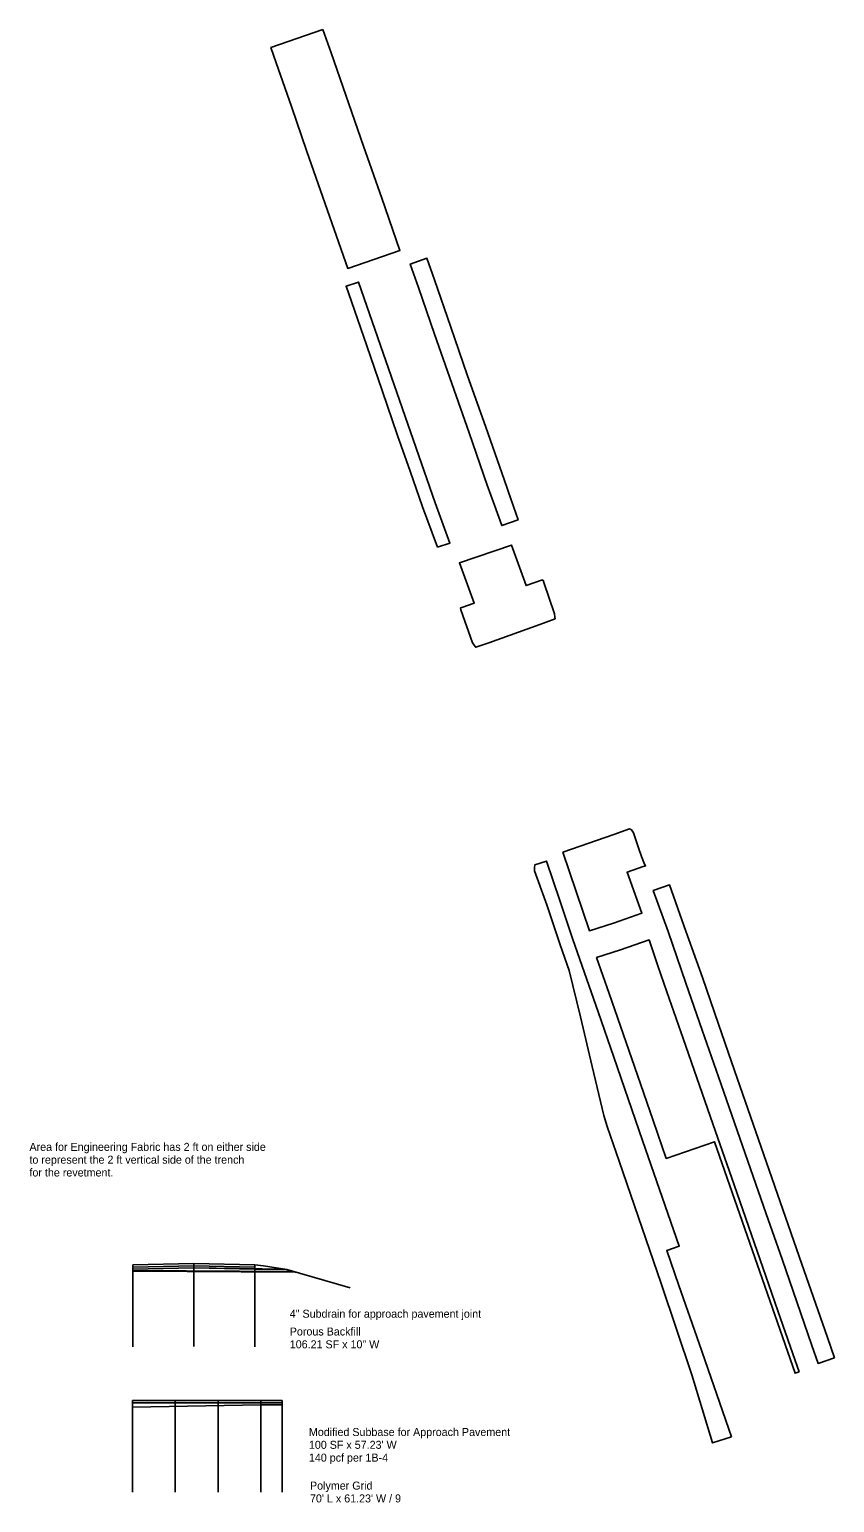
# Model space of a CAD drawing. Extents: x 16416320 to 16418266, y 7115195 to 7120678.
# Drawn here: x 16417426 to 16417803, y 7117848 to 7118538 of the extents above; entities that cross this region are included whole.
import ezdxf

# ---------------------------------------------------------------- set-up
doc = ezdxf.new("R2010")
doc.units = 0
for name, color, linetype in [('Default', 7, 'Continuous'), ('PS_BOLT', 7, 'Continuous'), ('PS_SHAPE', 7, 'Continuous'), ('PS_WORKFRAME', 7, 'Continuous'), ('Terrain', 7, 'Continuous')]:
    doc.layers.add(name, color=color, linetype=linetype)

msp = doc.modelspace()

# ---------------------------------------------------------------- linework, layer by layer
at = {"layer": 'Default'}
for p, q in [((16417474.07, 7117959), (16417502.68, 7117959.57)), ((16417474.07, 7117959), (16417474.07, 7117920.58)), ((16417474.07, 7117958), (16417502.68, 7117958.57)), ((16417474.07, 7117957), (16417502.68, 7117957.57)), ((16417502.68, 7117959.57), (16417502.68, 7117920.74)), ((16417531.3, 7117959), (16417502.68, 7117959.57)), ((16417531.3, 7117958), (16417502.68, 7117958.57)), ((16417531.3, 7117957), (16417502.68, 7117957.57)), ((16417531.3, 7117959), (16417531.3, 7117920.58)), ((16417531.3, 7117959), (16417535.3, 7117958.6)), ((16417531.3, 7117957), (16417545.32, 7117956.93)), ((16417535.3, 7117958.6), (16417546.19, 7117956.78)), ((16417474.09, 7117956.33), (16417549.08, 7117955.95)), ((16417474.09, 7117956), (16417550.27, 7117955.62)), ((16417546.19, 7117956.78), (16417575.9, 7117948.29)), ((16417474.02, 7117895.4), (16417474.02, 7117852.47)), ((16417474.02, 7117895.4), (16417544.02, 7117895.4)), ((16417494.02, 7117895.4), (16417494.02, 7117852.47)), ((16417514.02, 7117895.4), (16417514.02, 7117852.47)), ((16417534.02, 7117895.4), (16417534.02, 7117852.47)), ((16417544.02, 7117895.4), (16417544.02, 7117852.47)), ((16417474.02, 7117894.4), (16417544.02, 7117894.4)), ((16417474.02, 7117892.4), (16417534.02, 7117893.4)), ((16417534.02, 7117893.4), (16417544.02, 7117893.4))]:
    msp.add_line(p, q, dxfattribs=at)
msp.add_lwpolyline([(16417474.09, 7117956), (16417550.27, 7117955.62), (16417549.08, 7117955.95), (16417474.09, 7117956.33)], close=True, dxfattribs=at)
at = {"layer": 'PS_BOLT'}
for points in [[(16417563.16, 7118537.73), (16417566.98, 7118526.75), (16417582.13, 7118483.1), (16417590.67, 7118458.64), (16417599.21, 7118434.19), (16417574.74, 7118425.82), (16417555.65, 7118480.53), (16417548.47, 7118501.57), (16417541.32, 7118522.15), (16417538.83, 7118529.28)], [(16417654.54, 7118307.97), (16417646.89, 7118305.32), (16417643.5, 7118314.81), (16417640.11, 7118324.3), (16417631.57, 7118348.76), (16417615.45, 7118395.04), (16417607.88, 7118416.87), (16417604.06, 7118427.85), (16417611.87, 7118430.56), (16417615.37, 7118420.4), (16417623.03, 7118398.2), (16417630.68, 7118376), (16417639.38, 7118351.44), (16417648.07, 7118326.88), (16417651.31, 7118317.42)], [(16417616.8, 7118295.14), (16417616.8, 7118295.14), (16417609.73, 7118314.09), (16417603.93, 7118330.79), (16417598.13, 7118347.49), (16417590.89, 7118368.54), (16417583.66, 7118389.59), (16417576.47, 7118410.35), (16417574.02, 7118417.42), (16417579.73, 7118419.4), (16417615.64, 7118315.94), (16417622.59, 7118297.05)], [(16417671.81, 7118261.67), (16417664.77, 7118258.94), (16417640.75, 7118250.45), (16417634.77, 7118248.36), (16417634.5, 7118248.58), (16417634.45, 7118248.72), (16417633.17, 7118250.45), (16417627.73, 7118265.88), (16417627.56, 7118266.85), (16417628.18, 7118267.01), (16417633.91, 7118268.9), (16417633.96, 7118268.93), (16417627.02, 7118287.81), (16417651.49, 7118296.17), (16417658.27, 7118277.19), (16417665.92, 7118279.84), (16417665.91, 7118279.62), (16417666.24, 7118279.71), (16417666.63, 7118278.66), (16417669.09, 7118271.35), (16417671.54, 7118264.05), (16417671.75, 7118262.37)], [(16417675.54, 7118152.26), (16417699.28, 7118160.61), (16417706.76, 7118163.3), (16417707.6, 7118162.74), (16417708.61, 7118161.38), (16417710.99, 7118153.95), (16417712.32, 7118150.36), (16417713.66, 7118146.77), (16417714.21, 7118145.92), (16417713.68, 7118145.7), (16417713.15, 7118145.57), (16417705.52, 7118142.91), (16417712.52, 7118123.77), (16417699.16, 7118119.05), (16417687.93, 7118115.51)], [(16417754.43, 7117878.48), (16417745.58, 7117875.63), (16417735.91, 7117907.55), (16417721.53, 7117950.3), (16417721.53, 7117950.3), (16417701.81, 7118007.59), (16417696.23, 7118023.8), (16417694.71, 7118029.02), (16417689.2, 7118051.88), (16417683.68, 7118075.2), (16417678.47, 7118096.92), (16417674.27, 7118108.93), (16417668, 7118127.61), (16417662.27, 7118143.59), (16417662.16, 7118145.46), (16417662.39, 7118146.08), (16417662.42, 7118146.42), (16417667.8, 7118148.12), (16417673.99, 7118129.74), (16417680.19, 7118111.37), (16417691.97, 7118077.51), (16417699.36, 7118056.23), (16417712.8, 7118017.21), (16417729.97, 7117967.76), (16417724.13, 7117965.73), (16417729.84, 7117949.3), (16417739.28, 7117922.11)], [(16417802.68, 7117915.48), (16417795.01, 7117912.82), (16417792.05, 7117921.29), (16417778.13, 7117961.69), (16417770.75, 7117982.83), (16417763.37, 7118003.98), (16417748.42, 7118047.02), (16417740.76, 7118068.96), (16417733.11, 7118090.9), (16417724.81, 7118115.21), (16417717.81, 7118134.36), (16417725.43, 7118137.01), (16417733.13, 7118115.32), (16417740.82, 7118093.62), (16417748.37, 7118071.8), (16417755.92, 7118049.99), (16417763.38, 7118028.5), (16417770.84, 7118007.01), (16417778.48, 7117984.97), (16417786.12, 7117962.93), (16417799.38, 7117924.91)], [(16417786.05, 7117908.85), (16417784.22, 7117908.21), (16417746.54, 7118016.71), (16417723.87, 7118008.83), (16417717.83, 7118026.57), (16417710.43, 7118047.85), (16417697.15, 7118086.06), (16417691.26, 7118102.98), (16417702.49, 7118106.52), (16417709.17, 7118108.88), (16417715.85, 7118111.24), (16417720, 7118099.09), (16417724.15, 7118086.93), (16417731.81, 7118064.99), (16417739.46, 7118043.05), (16417746.94, 7118021.53), (16417754.41, 7118000.01), (16417769.17, 7117957.72), (16417776.13, 7117937.52), (16417783.09, 7117917.32)]]:
    msp.add_lwpolyline(points, close=True, dxfattribs=at)
at = {"layer": 'PS_SHAPE'}
msp.add_lwpolyline([(16417474.09, 7117956), (16417474.07, 7117957), (16417502.68, 7117957.57), (16417545.32, 7117956.93), (16417546.19, 7117956.78), (16417550.27, 7117955.62)], close=True, dxfattribs=at)
at = {"layer": 'PS_WORKFRAME'}
msp.add_lwpolyline([(16417474.02, 7117892.4), (16417474.02, 7117894.4), (16417544.02, 7117894.4), (16417544.02, 7117893.4), (16417534.02, 7117893.4)], close=True, dxfattribs=at)

# ---------------------------------------------------------------- texts
at = {"layer": 'Default'}
for s, p in [('4" Subdrain for approach pavement joint', (16417547.62, 7117934.24)), ('Polymer Grid', (16417557.09, 7117853.72)), ("70' L x 61.23' W / 9", (16417557.09, 7117847.72))]:
    msp.add_text(s, height=3.75, dxfattribs=at).set_placement(p)
at = {"layer": 'PS_SHAPE'}
for s, p in [('Porous Backfill', (16417547.62, 7117925.91)), ('106.21 SF x 10" W', (16417547.62, 7117919.91))]:
    msp.add_text(s, height=3.75, dxfattribs=at).set_placement(p)
at = {"layer": 'PS_WORKFRAME'}
for s, p in [('Modified Subbase for Approach Pavement', (16417556.58, 7117878.83)), ("100 SF x 57.23' W", (16417556.58, 7117872.83)), ('140 pcf per 1B-4', (16417556.58, 7117866.83))]:
    msp.add_text(s, height=3.75, dxfattribs=at).set_placement(p)
at = {"layer": 'Terrain'}
for s, p in [('Area for Engineering Fabric has 2 ft on either side', (16417425.74, 7118012.4)), ('to represent the 2 ft vertical side of the trench', (16417425.74, 7118006.4)), ('for the revetment.', (16417425.74, 7118000.4))]:
    msp.add_text(s, height=3.75, dxfattribs=at).set_placement(p)

doc.saveas('drawing.dxf')
